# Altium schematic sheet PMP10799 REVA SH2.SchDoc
size 431 x 279 mm; Date: Not shown in title block; ApprovedBy: Not shown in title block; CheckedBy: Not shown in title block; Author: Not shown in title block; CompanyName: Not shown in title block; Engineer: Not shown in title block; Organization: Not shown in title block; Address1: Not shown in title block; Address2: Not shown in title block; Address3: Not shown in title block; Address4: Not shown in title block; DocumentNumber: 2; Revision: Use project parameter SCH_Rev; SheetNumber: 2; SheetTotal: 2; PageSetup: Record=PageOptions¦CenterHorizontal=True¦CenterVertical=True¦PrintScale=1.00¦XCorrection=1.00¦YCorrection=1.00¦PrintKind=0¦BorderSize=5000000¦LeftOffset=0¦BottomOffset=0¦Orientation=2¦PaperLength=1000¦PaperWidth=1000¦Scale=100¦PaperSource=15¦PrintQuality=600¦MediaType=1¦DitherType=10¦PaperKind=Letter¦PrintScaleMode=1
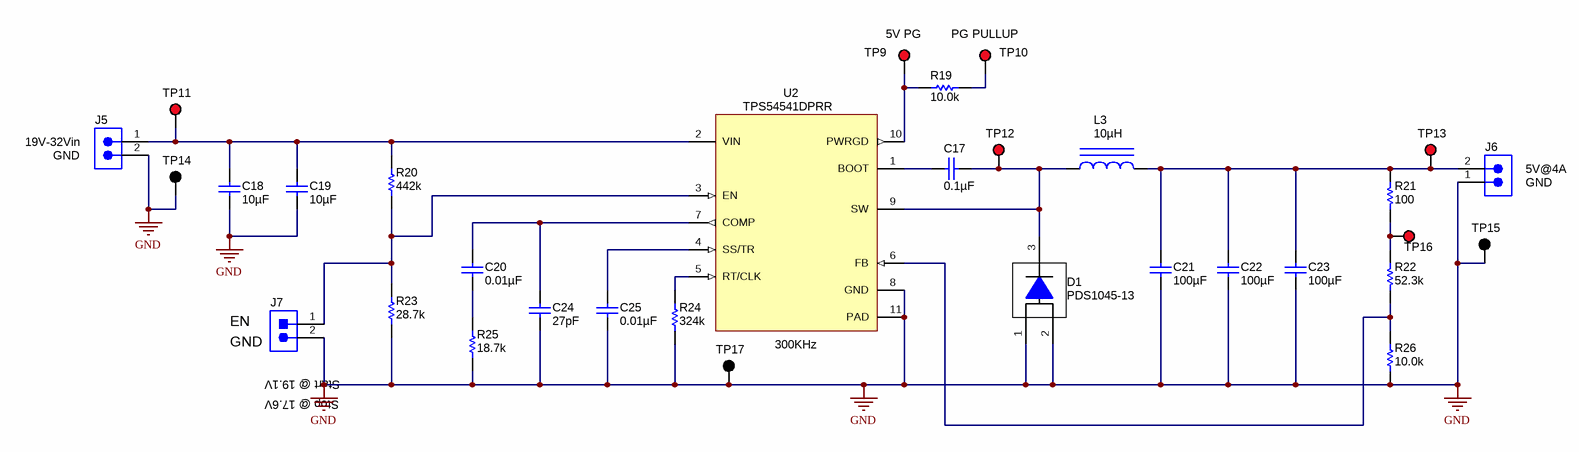
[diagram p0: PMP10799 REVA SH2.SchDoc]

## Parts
C17  ValueDisplayed: 0.1µF  [0603]  (hidden comment: C1608X7R1H104K)
C18  ValueDisplayed: 10µF  [1210]  (hidden comment: GRM32ER61H106MA12)
C19  ValueDisplayed: 10µF  [1210]  (hidden comment: GRM32ER61H106MA12)
C20  ValueDisplayed: 0.01µF  [0603]  (hidden comment: C1608X7R1H103K)
C21  ValueDisplayed: 100µF  [1210]  (hidden comment: GRM32EC80J107ME20)
C22  ValueDisplayed: 100µF  [1210]  (hidden comment: GRM32EC80J107ME20)
C23  ValueDisplayed: 100µF  [1210]  (hidden comment: GRM32EC80J107ME20)
C24  ValueDisplayed: 27pF  [0603]  (hidden comment: C1608C0G1H270J)
C25  ValueDisplayed: 0.01µF  [0603]  (hidden comment: C1608X7R1H103K)
D1  PDS1045-13  [PowerDI5]
J5  ED555/2DS  [TERM_BLK_ED555-2DS]  (value not drawn)
J6  ED555/2DS  [TERM_BLK_ED555-2DS]  (value not drawn)
J7  PEC02SAAN  [CONN_PEC02SAAN]  (value not drawn)
L3  ValueDisplayed: 10µH  [XAL8080_656]  (hidden comment: XAL8080-103ME)
R19  ValueDisplayed: 10.0k  [0603]  (hidden comment: CRCW060310K0FKEA)
R20  ValueDisplayed: 442k  [0603]  (hidden comment: CRCW0603442KFKEA)
R21  ValueDisplayed: 100  [0603L]  (hidden comment: CRCW0603100RFKEA)
R22  ValueDisplayed: 52.3k  [0603L]  (hidden comment: CRCW060352K3FKEA)
R23  ValueDisplayed: 28.7k  [0603]  (hidden comment: CRCW060328K7FKEA)
R24  ValueDisplayed: 324k  [0603]  (hidden comment: CRCW0603324KFKEA)
R25  ValueDisplayed: 18.7k  [0603]  (hidden comment: CRCW060318K7FKEA)
R26  ValueDisplayed: 10.0k  [0603L]  (hidden comment: CRCW060310K0FKEA)
TP9  5000  [Keystone5000]  (value not drawn)
TP10  5000  [Keystone5000]  (value not drawn)
TP11  5000  [Keystone5000]  (value not drawn)
TP12  5000  [Keystone5000]  (value not drawn)
TP13  5000  [Keystone5000]  (value not drawn)
TP14  5001  [Keystone5001]  (value not drawn)
TP15  5001  [Keystone5001]  (value not drawn)
TP16  5000  [Keystone5000]  (value not drawn)
TP17  5001  [Keystone5001]  (value not drawn)
U2  TPS54541DPRR  [DPR0010A]

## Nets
GND: C18.1 C19.1 C21.2 C22.2 C23.2 C24.2 C25.2 D1.1(A) D1.2(A) J5.2 J6.1 J7.2 R23.1 R24.1 R25.1 R26.1 TP14.1 TP15.1 TP17.1 U2.8(GND) U2.11(PAD)
NetC17_1: C17.1 U2.1(BOOT)
NetC17_2: C17.2 D1.3(K) L3.1 TP12.1 U2.9(SW)
NetC18_2: C18.2 C19.2 J5.1 R20.2 TP11.1 U2.2(VIN)
NetC20_1: C20.1 C24.1 U2.7(COMP)
NetC20_2: C20.2 R25.2
NetC21_1: C21.1 C22.1 C23.1 J6.2 L3.2 R21.2 TP13.1
NetC25_1: C25.1 U2.4(SS/TR)
NetJ7_1: J7.1 R20.1 R23.2 U2.3(EN)
NetR19_1: R19.1 TP10.1
NetR19_2: R19.2 TP9.1 U2.10(PWRGD)
NetR21_1: R21.1 R22.2 TP16.1
NetR22_1: R22.1 R26.2 U2.6(FB)
NetR24_2: R24.2 U2.5(RT/CLK)

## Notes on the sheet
- (near TP9) 5V PG
- (near TP10) PG PULLUP
- (near J5) 19V-32Vin
- (near J5) GND
- (near J6) 5V@4A
- (near J6) GND
- (near J7) EN
- (near J7) GND
- (near U2) 300KHz
- (near J7) Start @ 19.1V
- Stop @ 17.6V

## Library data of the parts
C17 = C1608X7R1H104K: CAP, CERM, 0.1uF, 50V, +/-10%, X7R, 0603; Manufacturer: TDK; Polarized: N; CompType: Capacitor; U/M: EA; Cap_F: 0.0000001; Tolerance_%: 10; ESR_Ohm: 0.017; Value1: 0.017 ohm; VDC_V: 50; TaMin_C: -55; TaMax_C: 125
C18 C19 = C3225X7R1E106M: CAP, CERM, 10uF, 50V, +/-20%, X5R, 1210; Manufacturer: MuRata; Polarized: N; CompType: Capacitor; U/M: EA; Cap_F: 0.00001; Tolerance_%: 20; ESR_Ohm: 0.0027; Value1: 0.0027 ohm; VDC_V: 50; IRMS_A: 3; TaMin_C: -55; TaMax_C: 125
C20 C25 = C1608X7R1H103K: CAP, CERM, 0.01 µF, 50 V, +/- 10%, X7R, 0603; Manufacturer: TDK; Polarized: N; CompType: Capacitor; Value: 0.01uF; U/M: EA; Cap_F: 0.00000001; Tolerance_%: 10; ESR_ohm: 0.0539; Value1: 0.0539 ohm; VDC_V: 50; Value2: 50V; TaMin_C: -55; TaMax_C: 125
C21-C23 = C3225X5R0J107M: CAP, CERM, 100 µF, 6.3 V, +/- 20%, X6S, 1210; Manufacturer: MuRata; Polarized: N; CompType: Capacitor; Value: 100uF; U/M: EA; Cap_F: 0.0001; Tolerance_%: 20; ESR_ohm: 0.002; Value1: 0.002 ohm; VDC_V: 6.3; Value2: 6.3V; IRMS_A: 3.5; TaMin_C: -55; TaMax_C: 85
C24 = C1608C0G1H270J: CAP, CERM, 27 pF, 50 V, +/- 5%, C0G/NP0, 0603; Manufacturer: TDK; Polarized: N; CompType: Capacitor; Value: 27pF; U/M: EA; Cap_F: 0.000000000027; Tolerance_%: 5; ESR_ohm: 0.327; Value1: 0.327 ohm; VDC_V: 50; Value2: 50V; TaMin_C: -55; TaMax_C: 125
D1 = PDS1045-13: Diode, Schottky, 45 V, 10 A, PowerDI5; Manufacturer: Diodes Inc.; SymbolCreator: a0412235; U/M: EA; Vf_V: 0.51; Value: 45V; Value1: 10A; Value2: 0.51V; Io_A: 10; Vr_V: 45; TJmax_C: 150; RJC_CperW: 85
J5 J6 = ED555/2DS: Terminal Block, 6A, 3.5mm Pitch, 2-Pos, TH; Manufacturer: On-Shore Technology, Inc.; SymbolCreator: a0412235; CompType: Connector; U/M: EA
J7 = PEC02SAAN: Header, 100mil, 2x1, Tin, TH; Manufacturer: Sullins Connector Solutions; SymbolCreator: a0412235; U/M: EA
L3 = XAL8080-472ME: Inductor, Shielded, Composite, 10 µH, 8.7 A, 0.021 ohm, SMD; Manufacturer: Coilcraft; Value: 10uH; Ind_H: 10E-6; Imax_A: 8.7; Irms: 6.6A @ 20C rise; Isat: 10.9A @ 20% inductance drop; DCR_ohm: 21; Value2: 8.7A
R19 R26 = CRCW060310K0FKEA: RES, 10.0 k, 1%, 0.1 W, 0603; Manufacturer: Vishay-Dale; CompType: Resistor; Value: 10.0k; Res_ohm: 10000; Value_Code: 10k0; Tolerance_%: 1; Power_W: 0.1; Value2: 0.1W; VDC_V: 75; TempCo: 100 ppm/C; EIA_Code: E96; U/M: EA
R20 = CRCW0603442KFKEA: RES, 442 k, 1%, 0.1 W, 0603; Manufacturer: Vishay-Dale; CompType: Resistor; Value: 442k; Res_ohm: 442000; Tolerance_%: 1; Power_W: 0.1; Value2: 0.1W; VDC_V: 75; TempCo: 100 ppm/C; EIA_Code: E96; U/M: EA
R21 = CRCW0603100RFKEA: RES, 100, 1%, 0.1 W, 0603; Manufacturer: Vishay-Dale; CompType: Resistor; Value: 100; Value_Code: 100R; Tolerance_%: 1; Power_W: 0.1; Value2: 0.1W; VDC_V: 75; TempCo: 100 ppm/C; EIA_Code: E96; U/M: EA
R22 = CRCW060352K3FKEA: RES, 52.3 k, 1%, 0.1 W, 0603; Manufacturer: Vishay-Dale; CompType: Resistor; Value: 52.3k; Res_ohm: 52300; Value_Code: 52k3; Tolerance_%: 1; Power_W: 0.1; Value2: 0.1W; VDC_V: 75; TempCo: 100 ppm/C; EIA_Code: E96; U/M: EA
R23 = CRCW060328K7FKEA: RES, 28.7 k, 1%, 0.1 W, 0603; Manufacturer: Vishay-Dale; CompType: Resistor; Value: 28.7k; Res_ohm: 28700; Value_Code: 28k7; Tolerance_%: 1; Power_W: 0.1; Value2: 0.1W; VDC_V: 75; TempCo: 100 ppm/C; EIA_Code: E96; U/M: EA
R24 = CRCW0603324KFKEA: RES, 324 k, 1%, 0.1 W, 0603; Manufacturer: Vishay-Dale; CompType: Resistor; Value: 324k; Res_ohm: 324000; Tolerance_%: 1; Power_W: 0.1; Value2: 0.1W; VDC_V: 75; TempCo: 100 ppm/C; EIA_Code: E96; U/M: EA
R25 = CRCW060318K7FKEA: RES, 18.7 k, 1%, 0.1 W, 0603; Manufacturer: Vishay-Dale; CompType: Resistor; Value: 18.7k; Res_ohm: 18700; Value_Code: 18k7; Tolerance_%: 1; Power_W: 0.1; Value2: 0.1W; VDC_V: 75; TempCo: 100 ppm/C; EIA_Code: E96; U/M: EA
TP9-TP13 TP16 = 5000: Test Point, TH, Miniature, Red; Manufacturer: Keystone; CompType: Test Point Loop; U/M: EA
TP14 TP15 TP17 = 5001: Test Point, TH, Miniature, Black; Manufacturer: Keystone; CompType: Test Point Loop; U/M: EA
U2 = TPS54361DPRQ1: 4.5-V to 42-V Input, 5-A, Step Down DC-DC Converter with Soft-Start and Eco-mode, DPR0010A; Alternate Manufacturer: None; Manufacturer: Texas Instruments; SymbolCreator: a0411947; CompType: IC; U/M: EA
